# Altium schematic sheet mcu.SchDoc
size A3
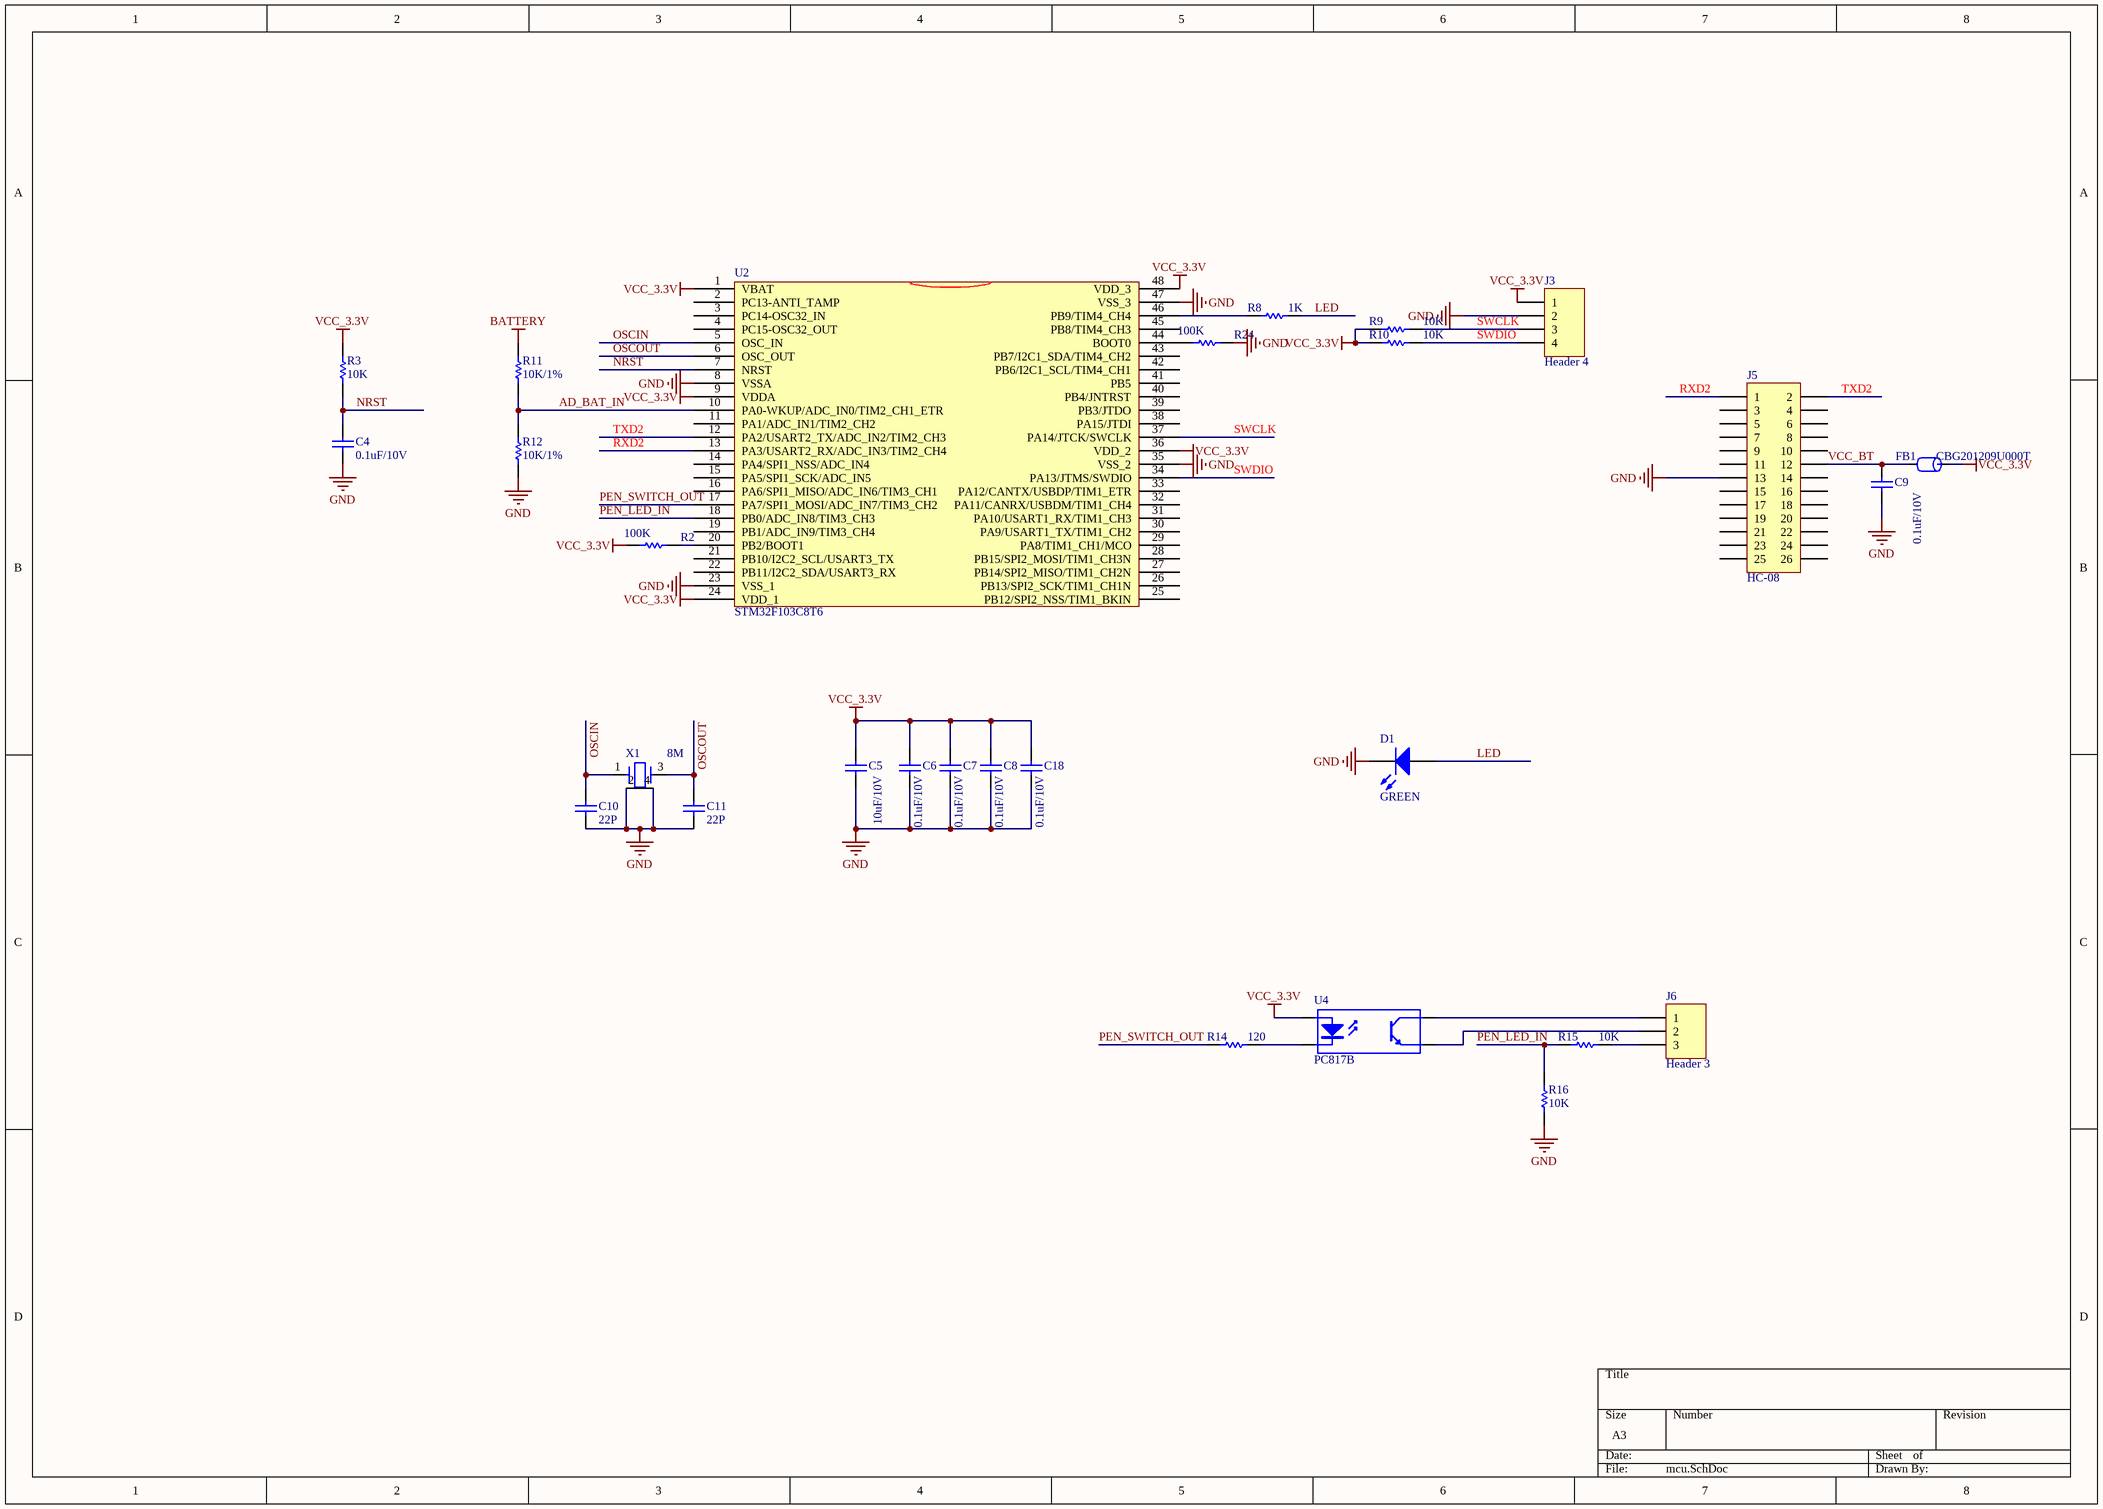
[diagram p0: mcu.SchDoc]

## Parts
C4  0.1uF/10V  [0402C]
C5  10uF/10V  [0603C]
C6  0.1uF/10V  [0402C]
C7  0.1uF/10V  [0402C]
C8  0.1uF/10V  [0402C]
C9  0.1uF/10V  [0402C]
C10  22P  [0402C]
C11  22P  [0402C]
C18  0.1uF/10V  [0402C]
D1  Publisher: GREEN  [0603LED]
FB1  CBG201209U000T  [0805CZ]
J3  Header 4  [mHDR1X4]
J5  HC-08  [HC-08V20/22/41]
J6  Header 3  [HDR1X3]
R2  100K  [0402R]
R3  10K  [0402R]
R8  1K  [0402R]
R9  10K  [0402R]
R10  10K  [0402R]
R11  10K/1%  [0402R]
R12  10K/1%  [0402R]
R14  120  [0402R]
R15  10K  [0402R]
R16  10K  [0402R]
R24  100K  [0402R]
U2  STM32F103C8T6  [TQFP-48]
U4  PC817B  [DIP-4]
X1  8M  [XTAL4TN_3225]

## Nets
BATTERY: R11.1
GND: C4.1 C5.1 C6.1 C7.1 C8.1 C9.1 C10.1 C11.1 C18.1 D1.2(K) J3.2 J5.13 R12.2 R16.1 R24.1 U2.8(VSSA) U2.23(VSS_1) U2.35(VSS_2) U2.47(VSS_3) X1.2(GND) X1.4(GND)
VCC_3.3V: C5.2 C6.2 C7.2 C8.2 C18.2 FB1.1 J3.1 R2.2 R3.1 R9.1 R10.1 U2.1(VBAT) U2.9(VDDA) U2.24(VDD_1) U2.36(VDD_2) U2.48(VDD_3) U4.1(A)
AD_BAT_IN: R11.2 R12.1 U2.10(PA0-WKUP/ADC_IN0/TIM2_CH1_ETR)
LED: D1.1(A) R8.2
NRST: C4.2 R3.2 U2.7(NRST)
OSCIN: C10.2 U2.5(OSC_IN) X1.1(X1)
OSCOUT: C11.2 U2.6(OSC_OUT) X1.3(X2)
PEN_LED_IN: R15.1 R16.2 U2.18(PB0/ADC_IN8/TIM3_CH3)
PEN_SWITCH_OUT: R14.1 U2.17(PA7/SPI1_MOSI/ADC_IN7/TIM3_CH2)
RXD2: J5.1 U2.13(PA3/USART2_RX/ADC_IN3/TIM2_CH4)
SWCLK: J3.3 R9.2 U2.37(PA14/JTCK/SWCLK)
SWDIO: J3.4 R10.2 U2.34(PA13/JTMS/SWDIO)
TXD2: J5.2 U2.12(PA2/USART2_TX/ADC_IN2/TIM2_CH3)
VCC_BT: C9.2 FB1.2 J5.12
NetJ6_1: J6.1 U4.4(C)
NetJ6_2: J6.2 U4.3(E)
NetJ6_3: J6.3 R15.2
NetR2_1: R2.1 U2.20(PB2/BOOT1)
NetR8_1: R8.1 U2.46(PB9/TIM4_CH4)
NetR14_2: R14.2 U4.2(K)
NetR24_2: R24.2 U2.44(BOOT0)

Not connected (* = marked no-connect by the designer): J5 3 4 5 6 7 8 9 10 11 14 15 16 17 18 19 20 21 22 23 24 25 26; U2 2(PC13-ANTI_TAMP) 3(PC14-OSC32_IN) 4(PC15-OSC32_OUT) 11(PA1/ADC_IN1/TIM2_CH2) 14(PA4/SPI1_NSS/ADC_IN4) 15(PA5/SPI1_SCK/ADC_IN5) 16(PA6/SPI1_MISO/ADC_IN6/TIM3_CH1) 19(PB1/ADC_IN9/TIM3_CH4) 21(PB10/I2C2_SCL/USART3_TX) 22(PB11/I2C2_SDA/USART3_RX) 25(PB12/SPI2_NSS/TIM1_BKIN) 26(PB13/SPI2_SCK/TIM1_CH1N) 27(PB14/SPI2_MISO/TIM1_CH2N) 28(PB15/SPI2_MOSI/TIM1_CH3N) 29(PA8/TIM1_CH1/MCO) 30(PA9/USART1_TX/TIM1_CH2) 31(PA10/USART1_RX/TIM1_CH3) 32(PA11/CANRX/USBDM/TIM1_CH4) 33(PA12/CANTX/USBDP/TIM1_ETR) 38(PA15/JTDI) 39(PB3/JTDO) 40(PB4/JNTRST) 41(PB5) 42(PB6/I2C1_SCL/TIM4_CH1) 43(PB7/I2C1_SDA/TIM4_CH2) 45(PB8/TIM4_CH3)

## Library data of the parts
C4-C11 C18 = Cap: Capacitor; Value: 100pF
D1 = LED0: Typical INFRARED GaAs LED
FB1 = FB: BLM21PG331SN1D
J3 = Header 4: Header, 4-Pin
J5 = Header 13X2: Header, 13-Pin, Dual row
J6 = Header 3: Header, 3-Pin
R2 R24 = Res1: Resistor
R3 R9-R12 R14-R16 = Res Semi: Semiconductor Resistor; Value: 1K
R8 = Res Semi: Semiconductor Resistor
U2 = STM32F103C6
U4 = Optoisolator1: 4-Pin Phototransistor Optocoupler
X1 = CRYSTAL-4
